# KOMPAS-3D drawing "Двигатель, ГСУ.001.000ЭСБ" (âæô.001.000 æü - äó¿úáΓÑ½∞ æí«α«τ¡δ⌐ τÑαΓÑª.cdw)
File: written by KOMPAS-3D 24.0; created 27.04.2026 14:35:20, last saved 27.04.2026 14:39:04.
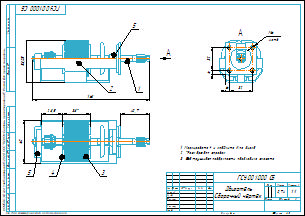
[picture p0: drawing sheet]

Document properties: Автор: USG_411; Форматы листов документа: A4; Полное имя файла: ГСУ.001.000 - Двигатель СП.spw; Масса: 0.738912; Наименование: Двигатель; Количество листов документа: 1

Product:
- Component [detail]: Рама двигателя  | designation ГСУ.001.001  | qty 1  | pos. 2  | Масса: 0.2349; Автор: USG_411; source file: ГСУ.001.001 ЭСБ - Рама двигателя.m3d
- Component [assembly]: Ротор  | designation ГСУ.001.100  | qty 1  | pos. 1  | Масса: 0.24841; Автор: USG_411; source file: ГСУ.001.100 ЭСБ - Ротор.a3d
- Component [detail]: Пластина  | designation ГСУ.001.005  | qty 2  | pos. 4  | Масса: 0.002575; Автор: USG_411; source file: ГСУ.001.005 ЭМД - Пластина.m3d
- Component [detail]: Основание статора  | designation ГСУ.001.002  | qty 1  | pos. 3  | Масса: 0.249145; Автор: USG_411; source file: ГСУ.001.002 ЭМД - Основание статора.m3d
- Component [detail]: Пластина держателя втулок  | designation ГСУ.001.013  | qty 2  | pos. 5  | Масса: 0.000654; Автор: USG_411; source file: ГСУ.001.013 ЭМД - Пластина держателя втулок.m3d
- Part/product: Двигатель  | designation ГСУ.001.000ЭСБ
    Масса: 0.738912
    Форматы листов документа: A4
    source file: ГСУ.001.000 - Двигатель СП.spw

Views: Вид 1, Вид:1, Вид по стрелке 4, Вид по стрелке А
Referenced files in C:\Users\USG_411.STUD\Desktop\ГМ2704_411-23\Двигатель мясорубки\: ГСУ.001.000 ЭСБ - Двигатель.a3d, ГСУ.001.001 ЭСБ - Рама двигателя.m3d, ГСУ.001.100 ЭСБ - Ротор.a3d, ГСУ.001.005 ЭМД - Пластина.m3d, ГСУ.001.002 ЭМД - Основание статора.m3d, ГСУ.001.013 ЭМД - Пластина держателя втулок.m3d, ГСУ.001.000 СБ - Двигатель Сборочный чертеж.cdw, ГСУ.001.101 ЭМД - Звёздочка.m3d, ГСУ.001.102 ЭМД - Вал ротора.m3d, ГСУ.001.103 ЭМД - Шестерёнка.m3d, ГСУ.001.104 ЭМД - Пропеллер.m3d, ГСУ.001.105 ЭМД - Коллектор.m3d, ГСУ.001.106 ЭМД - Шайба.m3d, ГСУ.001.107 ЭМД - Втулка.m3d, ГСУ.001.108 ЭМД - Пластина.m3d, ГСУ.001.110 ЭМД - Пластина.m3d
Referenced files in C:\Program Files\ASCON\KOMPAS-3D v21\Libs\PARTLib\DATA\vault\Methods\Kompas\3D\: PLib_Nut_OST92_900.m3d
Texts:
  Позиции 1
  objid
  viewid
  key
  prop
  position
  ГСУ.001.000
  Программные изделия  и базы данных
  Принадлежности
  Приспособления
  Упаковка
  ГСУ.001.001
  Рама двигателя
  ГСУ.001.001 ЭМД
  ГСУ.001.100
  Ротор
  ГСУ.001.100 ЭСБ
  ГСУ.001.005
  Пластина
  ГСУ.001.005 ЭМД
  ГСУ.001.002
  Основание статора
  ГСУ.001.002 ЭМД
  ГСУ.001.013
  Пластина держателя втулок
  ГСУ.001.013 ЭМД
  ГСУ.001.000
  Двигатель
  Сборочный чертеж
  ГСУ.001.001 Рама двигателя
  Звёздочка
  ГСУ.001.101
  ГСУ.001.101 Звёздочка
  Вал ротора
  ГСУ.001.102
  ГСУ.001.102 Вал ротора
  Модель ВиМП
  Шестерёнка
  ГСУ.001.103
  ГСУ.001.103 Шестерёнка
  Пропеллер
  ГСУ.001.104
  ГСУ.001.104 Пропеллер
  Коллектор
  ГСУ.001.105
  ГСУ.001.105 Коллектор
  Шайба
  ГСУ.001.106
  ГСУ.001.106 Шайба
  Втулка
  ГСУ.001.107
  ГСУ.001.107 Втулка
  ГСУ.001.108
  ГСУ.001.108 Пластина
  ГСУ.001.110
  ГСУ.001.110 Пластина
  Гайка М4-6H ГОСТ 15523-70
  ГСУ.001.100 Ротор
  ГСУ.001.005 Пластина
  ГСУ.001.002 Основание статора
  ГСУ.001.013 Пластина держателя втулок
  ЭСБ
  ГСУ.001.000 ЭСБ Двигатель
Dimensions and other numbers on the sheet: 0; 3; 2; 4; 162; 58,05; 651; 5; 1; 6; 4 отв.; 32; 1:1; 0,74

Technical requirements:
  Маркировать Ч и клеймить К на бирке.
  GOST Type AU
  *Размеры для справок.
  Все трущиеся поверхности необходимо смазать.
